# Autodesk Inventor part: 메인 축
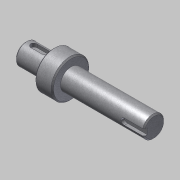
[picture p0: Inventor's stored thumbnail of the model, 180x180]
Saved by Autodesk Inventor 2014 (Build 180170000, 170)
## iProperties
Created: 2016-04
Part Number: 메인 축
Document SubType Name: Modeling
Designer: mdu
Density: 7.86 g/cm^3
Mass: 230.24 g
Surface Area: 74.3518 cm^2
Volume: 29.2926 cm^3
Material: 강철, 연강
Appearance: 금속-강(스테인리스, 브러시됨)
Author: mdu
Revision Number: 1
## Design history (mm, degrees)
sketch "스케치1"
  geometry: L1 (10.497, -57.5)-(112.497, -57.5); L2 (10.497, -66)-(32.497, -66); L3 (32.497, -72.5)-(46.5, -72.5); L4 (46.5, -66)-(112.497, -66); L5 (112.497, -66)-(112.497, -57.5); L6 (10.497, -66)-(10.497, -57.5); L7 (46.5, -69.749)-(46.5, -45.251) reference; L8 (46.5, -72.5)-(46.5, -66); L9 (32.497, -72.5)-(32.497, -66); L10 (32.497, -35)-(32.497, -80) reference; 3 further points
  constraints: 16 end point, 3 point on line, 2 parallel, 2 perpendicular, 1 collinear, 1 horizontal, 1 midpoint
  dimensions: "d0" = 17 diameter of L4 L1; "d1" = 30 diameter of L3 L1; "d2" = 22 distance of L2.start L2.end; "d3" = 65.99692 distance of L4.start L4.end (derived); "d5" = 17 diameter of L2 L1; "d19" = 80 distance between parallel lines of L5 L9
revolve "회전1" sketch "스케치1" stored, may be unused: angle "d4" = 90 deg
chamfer "모따기1" distance "d6" = 1; stored, may be unused: second distance "d7" = 2, angle "d8" = 45 deg
node "작업 평면1"
sketch "스케치2"
  geometry: L1 (-11, -7.5)-(-11, 7.5) reference; L2 (-4.5, 2.5)-(4.5, 2.5); L3 (4.5, -2.5)-(-4.5, -2.5); A1 r 2.5 centre (4.5, 0) between (4.5, -2.5) and (4.5, 2.5); A2 r 2.5 centre (-4.5, 0) between (-4.5, 2.5) and (-4.5, -2.5); 2 further points
  constraints: 4 end point, 4 point on circle, 4 tangent, 2 centre point, 1 horizontal alignment, 1 midpoint, 1 parallel, 1 perpendicular
  dimensions: "d9" = 5 distance between parallel lines of L3 L2; "d10" = 14 dimension on A1 A2; "d11" = 4 distance edge to line of A2 L1
extrude "돌출1" cut sketch "스케치2" distance "d12" = 3; taper "d13" = 0 deg
node "작업 평면2"
sketch "스케치3"
  geometry: L1 (32.998, 7.5)-(32.998, -7.5) reference; L2 (32.998, 2.5)-(17.498, 2.5); L3 (17.498, -2.5)-(32.998, -2.5); A1 r 2.5 centre (17.498, 0) between (17.498, 2.5) and (17.498, -2.5); 2 further points
  constraints: 4 end point, 2 perpendicular, 2 point on circle, 2 point on line, 2 tangent, 1 centre point, 1 horizontal alignment, 1 midpoint
  dimensions: "d14" = 5 distance between parallel lines of L3 L2; "d15" = 18 dimension on A1 L1
extrude "돌출2" cut sketch "스케치3" distance "d16" = 3; taper "d17" = 0 deg
node "솔리드1"
node "참조4"
node "참조5"
